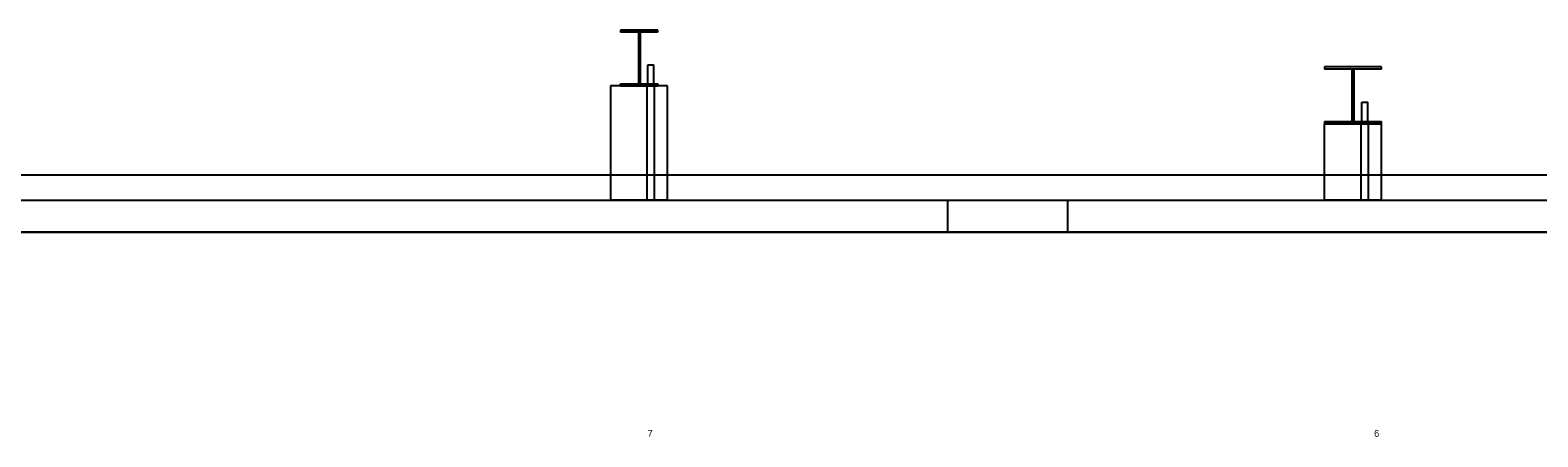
# Model space of a CAD drawing. Extents: x 49991 to 50160, y 49948 to 50051.
# Drawn here: x 50067.89 to 50081.09, y 50019.63 to 50023.19 of the extents above; entities that cross this region are included whole.
import ezdxf

# ---------------------------------------------------------------- set-up
doc = ezdxf.new("R2010")
doc.units = 0
for name, color, linetype in [('Level 1', 7, 'Continuous'), ('Level 3', 7, 'Continuous'), ('Level 4', 7, 'Continuous')]:
    doc.layers.add(name, color=color, linetype=linetype)

msp = doc.modelspace()

# ---------------------------------------------------------------- linework, layer by layer
at = {"layer": 'Level 1'}
for p, q in [((50073.39, 50023.188), (50073.061, 50023.188)), ((50073.061, 50023.188), (50073.061, 50023.172)), ((50073.39, 50023.172), (50073.061, 50023.172)), ((50073.218, 50023.172), (50073.218, 50022.719)), ((50073.233, 50023.172), (50073.233, 50022.719)), ((50073.39, 50023.172), (50073.39, 50023.188)), ((50073.301, 50022.885), (50073.353, 50022.885)), ((50073.301, 50022.719), (50073.301, 50022.885)), ((50073.353, 50022.719), (50073.353, 50022.885)), ((50079.723, 50022.869), (50079.223, 50022.869)), ((50079.223, 50022.869), (50079.223, 50022.848)), ((50079.723, 50022.848), (50079.223, 50022.848)), ((50079.463, 50022.848), (50079.463, 50022.391)), ((50079.483, 50022.391), (50079.483, 50022.848)), ((50079.723, 50022.848), (50079.723, 50022.869)), ((50073.473, 50022.702), (50072.973, 50022.702)), ((50072.973, 50022.702), (50072.973, 50021.702)), ((50073.061, 50022.702), (50073.061, 50022.719)), ((50073.061, 50022.719), (50073.39, 50022.719)), ((50073.061, 50022.702), (50073.39, 50022.702)), ((50073.39, 50022.719), (50073.39, 50022.702)), ((50073.473, 50021.702), (50073.473, 50022.702)), ((50079.551, 50022.558), (50079.603, 50022.558)), ((50079.551, 50022.391), (50079.551, 50022.558)), ((50079.603, 50022.391), (50079.603, 50022.558)), ((50079.223, 50022.391), (50079.223, 50022.369)), ((50079.223, 50022.391), (50079.723, 50022.391)), ((50079.223, 50022.369), (50079.723, 50022.369)), ((50079.723, 50022.369), (50079.223, 50022.369)), ((50079.223, 50021.703), (50079.223, 50022.369)), ((50079.723, 50022.369), (50079.723, 50022.391)), ((50079.723, 50021.703), (50079.723, 50022.369)), ((50067.223, 50021.922), (50072.973, 50021.922)), ((50073.473, 50021.922), (50079.223, 50021.922)), ((50079.723, 50021.922), (50085.473, 50021.922)), ((50034.588, 50021.704), (50093.827, 50021.702)), ((50073.473, 50021.702), (50072.973, 50021.702)), ((50075.927, 50021.422), (50075.927, 50021.702)), ((50079.723, 50021.703), (50079.223, 50021.703)), ((50038.316, 50021.423), (50093.827, 50021.42))]:
    msp.add_line(p, q, dxfattribs=at)
at = {"layer": 'Level 3'}
for p, q in [((50073.327, 50021.422), (50067.077, 50021.422)), ((50079.577, 50021.422), (50073.327, 50021.422)), ((50085.827, 50021.422), (50079.577, 50021.422))]:
    msp.add_line(p, q, dxfattribs=at)
at = {"layer": 'Level 4'}
for p, q in [((50073.296, 50021.702), (50073.296, 50022.702)), ((50073.358, 50021.702), (50073.358, 50022.702)), ((50079.546, 50021.703), (50079.546, 50022.369)), ((50079.608, 50021.703), (50079.608, 50022.369)), ((50072.973, 50021.922), (50073.473, 50021.922)), ((50079.223, 50021.922), (50079.723, 50021.922)), ((50076.977, 50021.422), (50076.977, 50021.702))]:
    msp.add_line(p, q, dxfattribs=at)

# ---------------------------------------------------------------- texts
at = {"layer": 'Level 3'}
for s, p in [('7', (50073.299, 50019.633)), ('6', (50079.658, 50019.633))]:
    msp.add_text(s, height=0.06, dxfattribs=at).set_placement(p)

doc.saveas('drawing.dxf')
